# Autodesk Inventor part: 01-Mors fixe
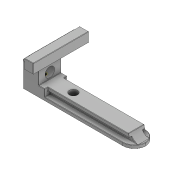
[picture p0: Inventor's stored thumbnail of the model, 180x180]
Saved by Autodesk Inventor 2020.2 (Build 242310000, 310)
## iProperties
Created: 2022-02
Part Number: 01-Mors fixe
Material: Fonte, moulé
Document SubType Name: Modeling
Designer: Philippe
Density: 7.15 g/cm^3
Appearance: Gris clair
Author: Philippe
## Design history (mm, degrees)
derived "Base-Etau.ipt"
sketch "Esquisse1"
  geometry: C1 r 2.458 at (0, 0) reference; A1 r 3 centre (0, 0) between (-3, 0) and (0, 3); 1 further point
  constraints: 2 point on circle, 1 centre point, 1 coincident, 1 horizontal alignment, 1 vertical alignment
  dimensions: "d1" = 3 radius of A1
feature "SrfExtrusion1" sketch "Esquisse1" dims "d2" = 1, "d3" = 10, "d4" = 0, "d5" = 0
feature "01-Mors fixe::Base-Etau.ipt" dims "d0" = 10
tag "FonctionRepérage1"
body "Srf1"
node "Solide1"
